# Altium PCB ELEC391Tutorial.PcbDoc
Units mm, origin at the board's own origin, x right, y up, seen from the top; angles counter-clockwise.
Board outline 30 x 30.13 mm, 2 copper layers (Top Layer, Bottom Layer), stack 1.569 mm thick; 9 components, 6 nets, 20 pads, 1 vias.
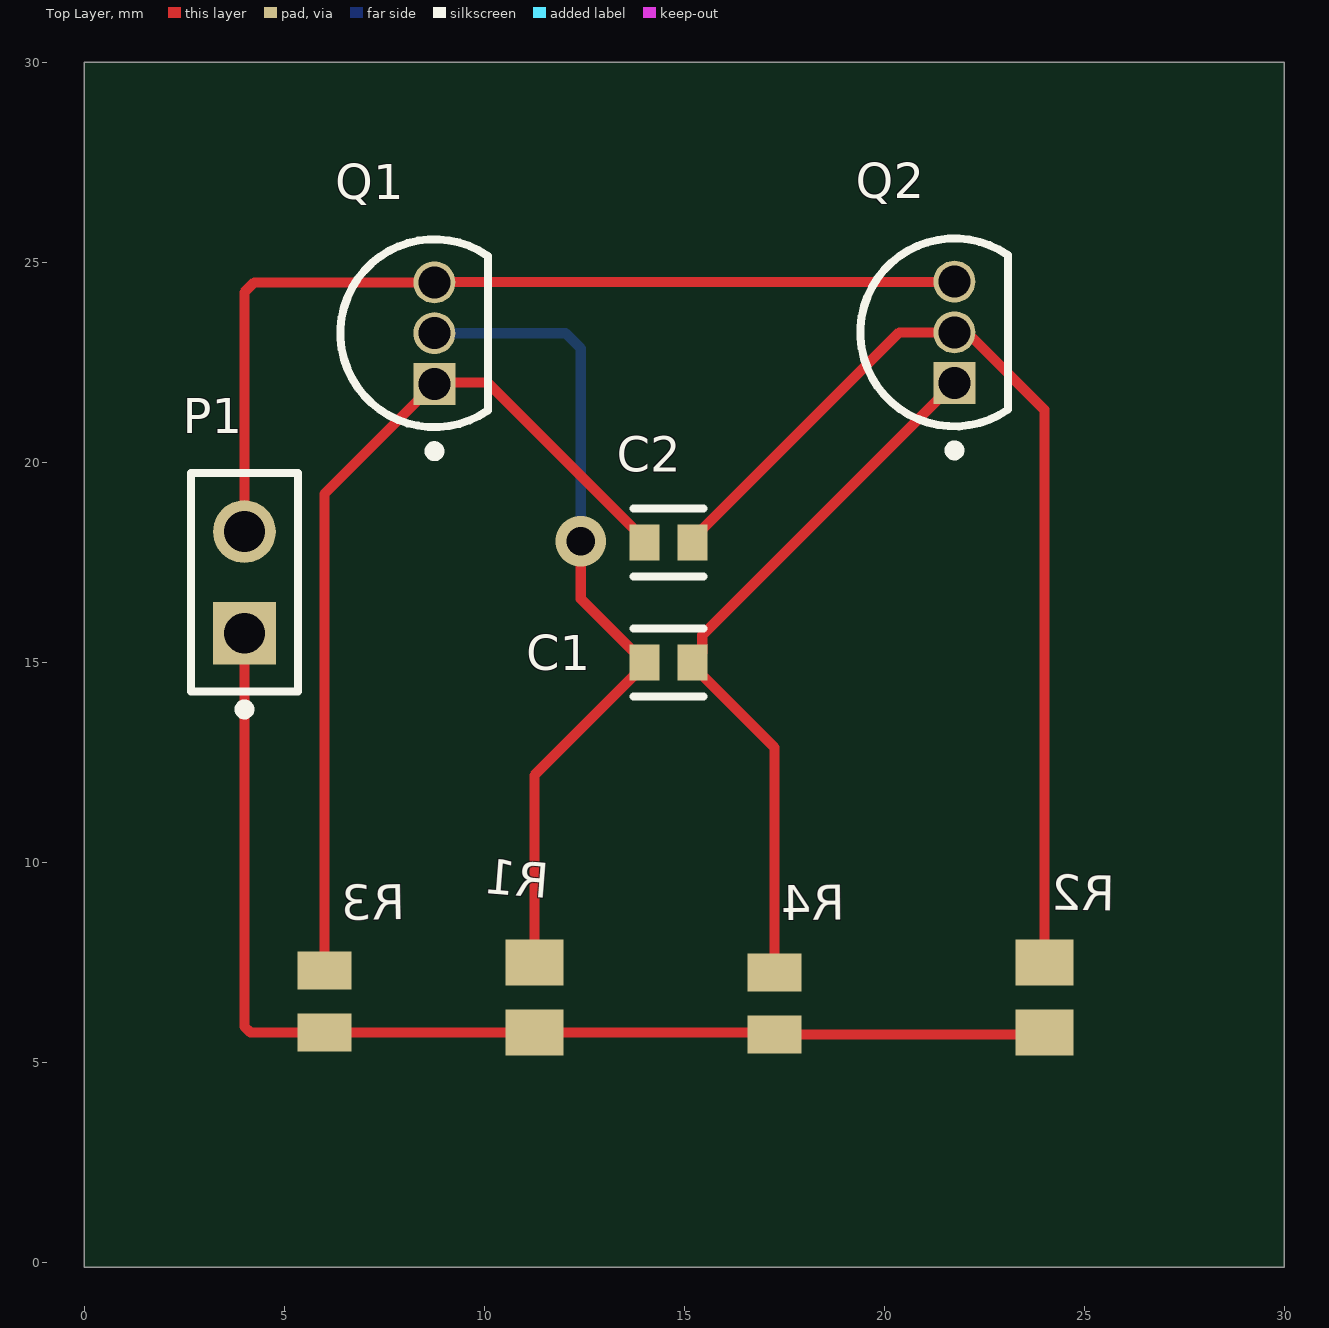
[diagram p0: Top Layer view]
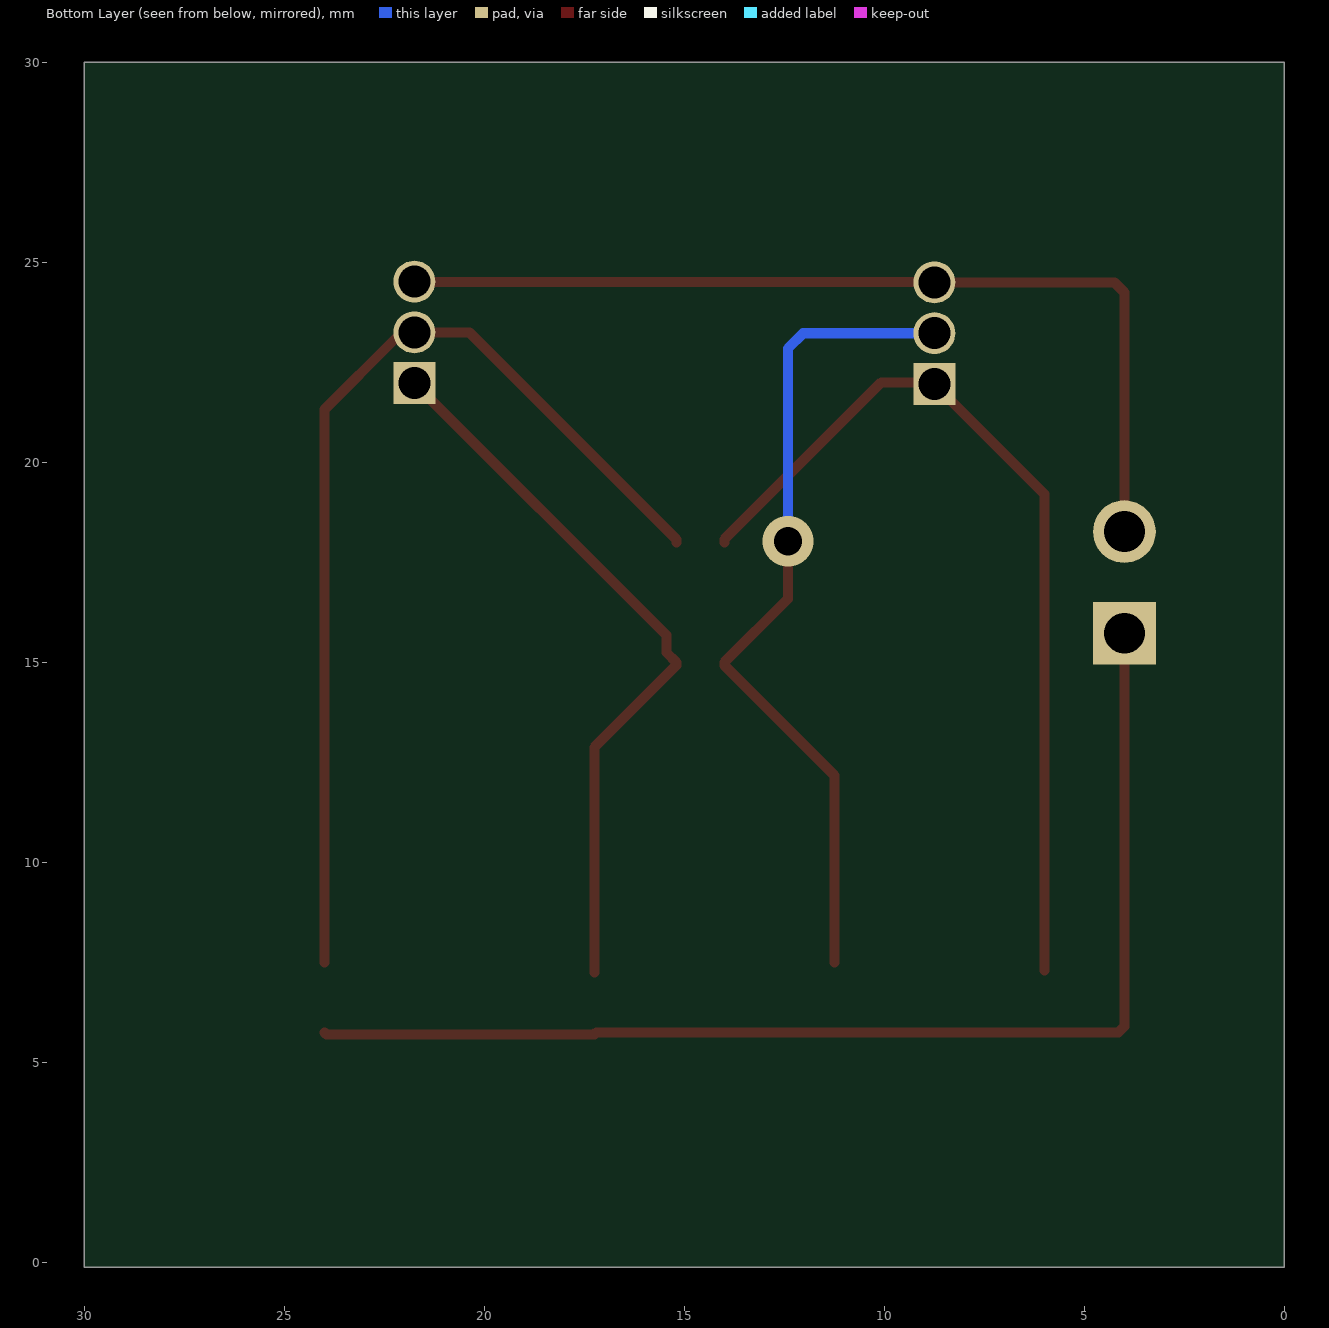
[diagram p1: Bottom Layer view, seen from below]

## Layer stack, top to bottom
Top Solder: solder mask 0.0254, SM-001, Dk 4
Top Layer: signal copper 0.035
Dielectric 1: core 1.4986, Core-043, Dk 4.3
Bottom Layer: signal copper 0.035
Bottom Solder: solder mask 0.0254, SM-001, Dk 4

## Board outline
0,-0.127 30,-0.127 30,30 0,30

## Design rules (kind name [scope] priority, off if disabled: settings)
AssemblyTestPointUsage [All] p1: isadvanced=TRUE
AssemblyTestpoint [All] p1: isadvanced=TRUE testpointundercomponent=TRUE minsize=1.016 maxsize=2.54 preferedsize=1.524 minholesize=0 maxholesize=1.016 preferedholesize=0.813 testpointgrid=0.025 usegrid=TRUE gridtolerance=0 allowsidetop=TRUE allowsidebottom=TRUE
Clearance Clearance_1 [OnMid vs OnMid] p1: gap=0.254 ignorepadtopadclearanceinfootprint=FALSE except(0.22: THPad-THPad) sourcerule=37 cellrowname=All cellrowtype=0 cellcolname=All cellcoltype=0 innerlayers=TRUE
Clearance Clearance_2 [(ExistsOnLayer('Top Layer') Or ExistsOnLayer('Bottom Layer')) vs (ExistsOnLayer('Top Layer') Or ExistsOnLayer('Bottom Layer'))] p2: gap=0.254 ignorepadtopadclearanceinfootprint=FALSE except(0.22: THPad-THPad) sourcerule=37 cellrowname=All cellrowtype=0 cellcolname=All cellcoltype=0 outerlayers=TRUE
Clearance [All] p3: gap=0.254 ignorepadtopadclearanceinfootprint=FALSE ismatrix=TRUE
ComponentClearance [All] p1: isadvanced=TRUE gap=0.254 collisioncheckmode=3 verticalgap=0.254 showdistances=FALSE
FabricationTestPointUsage [All] p1: isadvanced=TRUE valid=0 allowmultiple=FALSE
FabricationTestpoint [All] p1: isadvanced=TRUE side=3 testpointundercomponent=TRUE minsize=1.016 maxsize=2.54 preferedsize=1.524 minholesize=0 maxholesize=1.016 preferedholesize=0.813 testpointgrid=0.025 allowsidetop=TRUE allowsidebottom=TRUE usegrid=TRUE gridtolerance=0
FanoutControl Fanout_BGA [IsBGA] p1: isadvanced=TRUE bgadir=Out bgaviamode=Centered fanoutstyle=Auto fanoutdirection=Alternating viagrid=0.025 // Fanout_BGA (Default Rule)
FanoutControl Fanout_LCC [IsLCC] p2: isadvanced=TRUE bgadir=Out bgaviamode=Centered fanoutstyle=Auto fanoutdirection=Alternating viagrid=0.025 // Fanout_LCC (Default Rule)
FanoutControl Fanout_SOIC [IsSOIC] p3: isadvanced=TRUE bgadir=Out bgaviamode=Centered fanoutstyle=Auto fanoutdirection=Alternating viagrid=0.025 // Fanout_SOIC (Default Rule)
FanoutControl Fanout_Small [(CompPinCount < 5)] p4: isadvanced=TRUE bgadir=Out bgaviamode=Centered fanoutstyle=Auto fanoutdirection=OutThenIn viagrid=0.025 // Fanout_Small (Default Rule)
FanoutControl Fanout_Default [All] p5: isadvanced=TRUE bgadir=Out bgaviamode=Centered fanoutstyle=Auto fanoutdirection=Alternating viagrid=0.025 // Fanout_Default (Default Rule)
Height [All] p1: isadvanced=TRUE minheight=0 maxheight=25.4 prefheight=12.7
HoleSize [All] p1: isadvanced=TRUE absolutevalues=TRUE maxlimit=2.54 minlimit=0.025 maxpercent=80.000 minpercent=20.000
HoleToHoleClearance [All] p1: isadvanced=TRUE gap=0.254 allowstackedmicrovias=TRUE
LayerPairs [All] p1: isadvanced=TRUE enforce=TRUE
MinimumSolderMaskSliver [All] p1: isadvanced=TRUE minsoldermaskwidth=0.22
NetAntennae [All] p1: isadvanced=TRUE netantennaetolerance=0
PasteMaskExpansion [All] p1: isadvanced=TRUE expansion=0
PlaneClearance [All] p1: isadvanced=TRUE clearance=0.508
PlaneConnect [All] p1: isadvanced=TRUE planeconnectstyle=Relief reliefexpansion=0.508 reliefentries=4 reliefconductorwidth=0.254 reliefairgap=0.254
PolygonConnect [All] p1: connectstyle=Relief reliefconductorwidth=0.254 reliefentries=4 polygonreliefangle="90 Angle" airgapwidth=0.254
RoutingCorners [All] p1: isadvanced=TRUE cornerstyle=45-Degree minsetback=2.54 maxsetback=2.54
RoutingPriority [All] p1: isadvanced=TRUE routingpriority=0
RoutingVias [All] p1: holewidth=0.711 width=1.27 viastyle="Through Hole" minholewidth=0.711 minwidth=1.27 maxholewidth=0.711 maxwidth=1.27
ShortCircuit [All] p1: isadvanced=TRUE allowed=FALSE
SilkToSilkClearance [All] p1: isadvanced=TRUE silktosilkclearance=0.254
SilkToSolderMaskClearance [IsPad] p1: isadvanced=TRUE minsilkscreentomaskgap=0.254 clearancetoexposedcopper=TRUE
SolderMaskExpansion SolderMaskExpansion_Transistor [HasFootprint('ONSC-TO-92-3-29-11')] p1: isadvanced=TRUE expansion=0 istentingtop=FALSE useseparateexpansions=TRUE expansionbottom=0 istentingbottom=FALSE
SolderMaskExpansion [All] p2: isadvanced=TRUE expansion=0.102 istentingtop=FALSE
UnRoutedNet [All] p1: isadvanced=TRUE
UnpouredPolygon [All] p1: isadvanced=TRUE
Width [All] p1: maxlimit=0.254 minlimit=0.254 preferedwidth=0.254
4 further rules are at their usual default settings.

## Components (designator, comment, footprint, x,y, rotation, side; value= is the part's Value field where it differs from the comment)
C1 "C0603C223J4RACTU" FP-C0603C-CF-MFG 14.6,15 r0 top value="22,000 pF"
C2 "C0603C223J4RACTU" FP-C0603C-CF-MFG 14.6,18 r0 top value="22,000 pF"
P1 "TSW-102-07-F-S" FP-TSW-102-07-F-S-MFG 4,17 r90 top
Q1 "BC547CG" ONSC-TO-92-3-29-11 8.75,23.23 r90 top
Q2 "BC547CG" ONSC-TO-92-3-29-11 21.75,23.25 r90 top
R1 "ERJ-6GEYJ104V" RESC2013X70X40NL20T20 11.25,6.625 r270 top
R2 "ERJ-6GEYJ104V" RESC2013X70X40NL20T20 24,6.625 r270 top
R3 "ERJ-P06J102V" RESC2013X70X40LL20T20 6,6.525 r270 top
R4 "ERJ-P06J102V" RESC2013X70X40LL20T20 17.25,6.475 r270 top

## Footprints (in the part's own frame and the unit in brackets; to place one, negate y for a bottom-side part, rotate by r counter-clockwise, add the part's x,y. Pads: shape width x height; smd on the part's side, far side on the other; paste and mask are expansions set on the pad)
FP-C0603C-CF-MFG [mm]
  rect 0.75x0.9 smd paste+0 mask+0: 1(-0.6,0) 2(0.6,0)
  silkscreen extent -0.87,-0.85 0.88,0.85, body extent -1.2,-0.6 1.2,0.6, height 0.25
FP-TSW-102-07-F-S-MFG [mm]
  rect 1.57x1.57 hole 1.02 paste-2539.97 mask+0: 1(-1.27,0)
  round 1.57 hole 1.02 paste-2539.97 mask+0: 2(1.27,0)
  silkscreen extent -3.3,-1.34 2.73,1.34, body extent -2.83,-1.44 2.83,1.44, height 0.25
ONSC-TO-92-3-29-11 [mm] "TO, 3-Leads, Body Dia 4.7mm, Pitch 1.27mm"
  rect 1.05x1.05 hole 0.8: 1(-1.27,0)
  round 1.05 hole 0.8: 2(0,0) 3(1.27,0)
  silkscreen extent -3.07,-1.34 2.35,2.35, body extent -2.35,-1.33 2.36,2.36, height 7.87
RESC2013X70X40LL20T20 [mm] "Chip Resistor, 2-Leads, Body 2.00x1.25mm, IPC High Density"
  rect 0.95x1.35 smd: 1(-0.775,0) 2(0.775,0)
  body extent -1.1,-0.72 1.1,0.72, height 0.7
RESC2013X70X40NL20T20 [mm] "Chip Resistor, 2-Leads, Body 2.00x1.25mm, IPC Medium Density"
  rect 1.15x1.45 smd: 1(-0.875,0) 2(0.875,0)
  body extent -1.1,-0.72 1.1,0.72, height 0.7

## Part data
C1 C2: library part CMP-2006-03745-2, "CAP CER 0.022UF 16V 5% X7R 0603", Capacitance="22,000 pF", Manufacturer=KEMET, Package=C0603C-CF, Temperature="-55°C to +125°C", Temperature Characteristic=X7R, Temperature Coefficient=30ppm/°C, Temperature Range High=+125°C, Temperature Range Low=-55°C, Tolerance=0.05, Voltage Rating="16 V"
P1: library part CMP-002-00071-1, "Board Connector, 2 Contact(s), 1 Row(s), Male, Straight, 0.1 inch Pitch, Solder Terminal, Black Insulator"
Q1 Q2: library part CMP-1048-01464-1, "Amplifier Transistor, NPN Silicon, 3-Pin TO-92, Pb-Free, Bulk Box", Manufacturer="On Semiconductor"
R1 R2: library part CMP-2001-00338-1, Manufacturer=Panasonic
R3 R4: library part CMP-2001-00477-1, Manufacturer=Panasonic

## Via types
v1: diameter 1.27, hole 0.711, Top Layer to Bottom Layer, 1 vias

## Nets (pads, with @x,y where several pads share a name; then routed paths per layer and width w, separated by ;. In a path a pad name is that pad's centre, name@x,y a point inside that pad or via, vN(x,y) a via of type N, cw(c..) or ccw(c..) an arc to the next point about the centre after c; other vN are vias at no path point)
12V: P1.1 R1.2 R2.2 R3.2 R4.2 | length 29.9
  Top Layer w0.254: P1.1 4,5.899 4.149,5.75 R3.2 R1.2 17.2,5.75 R4.2 23.95,5.7 R2.2
GND: P1.2 Q1.3 Q2.3 | length 23.8
  Top Layer w0.254: P1.2 4,24.25 4.25,24.5 Q1.3 8.76,24.51 21.74,24.51 Q2.3
NetC1_1: C1.1 Q1.2 R1.1 | length 21.1
  Top Layer w0.254: Q1.2 Q1.2@8.843,23.137 ; R1.1 11.25,12.175 14,14.925 C1.1 12.41,16.59 v1(12.41,18.027)
  Bottom Layer w0.254: Q1.2 12.031,23.23 12.41,22.851 v1(12.41,18.027)
NetC1_2: C1.2 Q2.1 R4.1 | length 18.2
  Top Layer w0.254: C1.2@15.2,14.925 17.25,12.875 R4.1 ; C1.2 15.448,15.248 15.448,15.678 Q2.1
NetC2_1: C2.1 Q1.1 R3.1 | length 22.8
  Top Layer w0.254: R3.1 6,19.21 Q1.1 8.75,22 10.075,22 14,18.075 C2.1
NetC2_2: C2.2 Q2.2 R2.1 | length 25.6
  Top Layer w0.254: C2.2 15.2,18.075 20.375,23.25 Q2.2 21.902,23.098 22.221,23.098 24,21.319 R2.1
